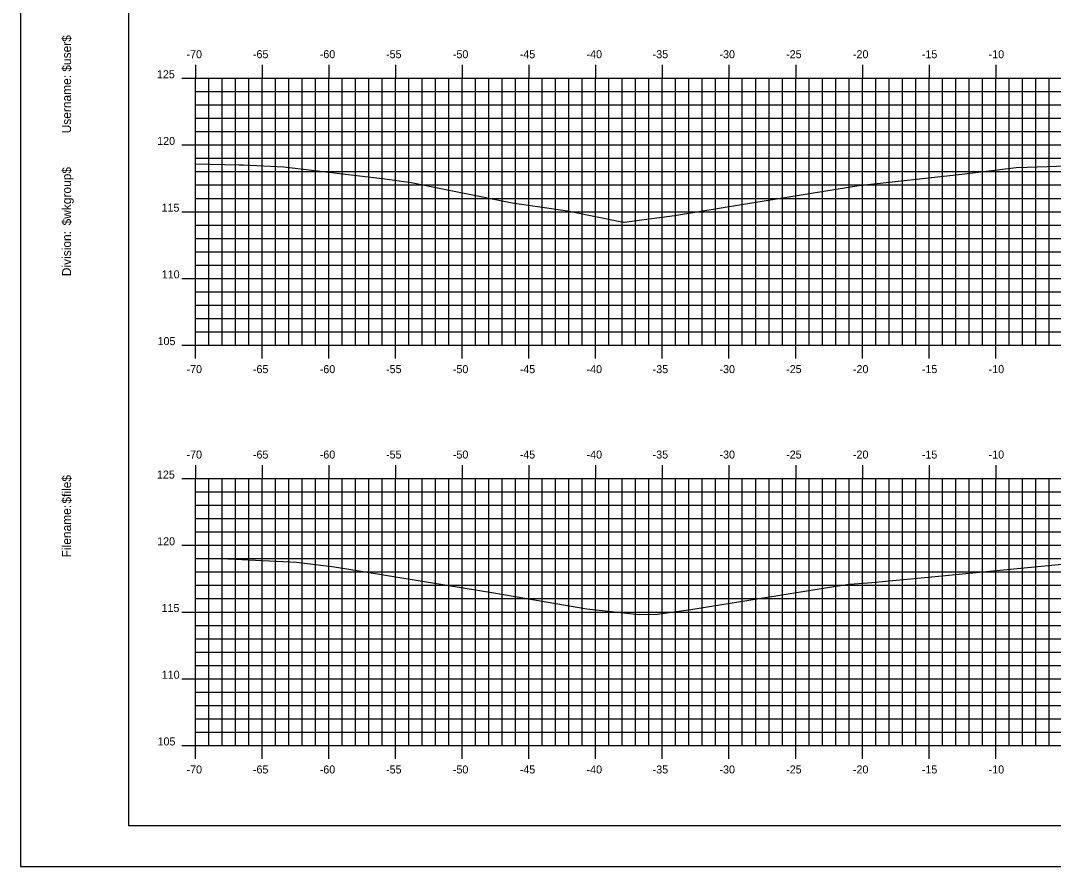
# Model space of a CAD drawing. Extents: x 853512 to 853684, y 365624 to 365734.
# Drawn here: x 853512.5 to 853589.9, y 365624 to 365687.3 of the extents above; entities that cross this region are included whole.
import ezdxf

# ---------------------------------------------------------------- set-up
doc = ezdxf.new("R2010")
doc.units = 0
for name, color, linetype in [('BORDER', 7, 'Continuous'), ('H_V ANNOTATION', 7, 'Continuous'), ('MAJOR', 7, 'Continuous'), ('MINOR', 7, 'Continuous'), ('PLOT BOUNDARY', 7, 'Continuous'), ('S_Roadway_Centerline', 7, 'Continuous')]:
    doc.layers.add(name, color=color, linetype=linetype)

msp = doc.modelspace()

# ---------------------------------------------------------------- linework, layer by layer
at = {"layer": 'BORDER'}
msp.add_lwpolyline([(853520.575, 365627.027), (853680.575, 365627.027), (853680.575, 365732.027), (853520.575, 365732.027)], close=True, dxfattribs=at)
at = {"layer": 'MAJOR'}
for p, q in [((853525.575, 365684.029), (853525.575, 365683.027)), ((853530.575, 365684.029), (853530.575, 365683.027)), ((853535.575, 365684.029), (853535.575, 365683.027)), ((853540.575, 365684.029), (853540.575, 365683.027)), ((853545.575, 365684.029), (853545.575, 365683.027)), ((853550.575, 365684.029), (853550.575, 365683.027)), ((853555.575, 365684.029), (853555.575, 365683.027)), ((853560.575, 365684.029), (853560.575, 365683.027)), ((853565.575, 365684.029), (853565.575, 365683.027)), ((853570.575, 365684.029), (853570.575, 365683.027)), ((853575.575, 365684.029), (853575.575, 365683.027)), ((853580.575, 365684.029), (853580.575, 365683.027)), ((853585.575, 365684.029), (853585.575, 365683.027)), ((853524.573, 365683.027), (853525.575, 365683.027)), ((853525.575, 365683.027), (853665.575, 365683.027)), ((853525.575, 365663.027), (853525.575, 365683.027)), ((853525.575, 365663.027), (853525.575, 365683.027)), ((853525.575, 365683.027), (853665.575, 365683.027)), ((853530.575, 365663.027), (853530.575, 365683.027)), ((853535.575, 365663.027), (853535.575, 365683.027)), ((853540.575, 365663.027), (853540.575, 365683.027)), ((853545.575, 365663.027), (853545.575, 365683.027)), ((853550.575, 365663.027), (853550.575, 365683.027)), ((853555.575, 365663.027), (853555.575, 365683.027)), ((853560.575, 365663.027), (853560.575, 365683.027)), ((853565.575, 365663.027), (853565.575, 365683.027)), ((853570.575, 365663.027), (853570.575, 365683.027)), ((853575.575, 365663.027), (853575.575, 365683.027)), ((853580.575, 365663.027), (853580.575, 365683.027)), ((853585.575, 365663.027), (853585.575, 365683.027)), ((853524.573, 365678.027), (853525.575, 365678.027)), ((853525.575, 365678.027), (853665.575, 365678.027)), ((853524.573, 365673.027), (853525.575, 365673.027)), ((853525.575, 365673.027), (853665.575, 365673.027)), ((853524.573, 365668.027), (853525.575, 365668.027)), ((853525.575, 365668.027), (853665.575, 365668.027)), ((853524.573, 365663.027), (853525.575, 365663.027)), ((853525.575, 365663.027), (853665.575, 365663.027)), ((853525.575, 365663.027), (853665.575, 365663.027)), ((853525.575, 365662.025), (853525.575, 365663.027)), ((853530.575, 365662.025), (853530.575, 365663.027)), ((853535.575, 365662.025), (853535.575, 365663.027)), ((853540.575, 365662.025), (853540.575, 365663.027)), ((853545.575, 365662.025), (853545.575, 365663.027)), ((853550.575, 365662.025), (853550.575, 365663.027)), ((853555.575, 365662.025), (853555.575, 365663.027)), ((853560.575, 365662.025), (853560.575, 365663.027)), ((853565.575, 365662.025), (853565.575, 365663.027)), ((853570.575, 365662.025), (853570.575, 365663.027)), ((853575.575, 365662.025), (853575.575, 365663.027)), ((853580.575, 365662.025), (853580.575, 365663.027)), ((853585.575, 365662.025), (853585.575, 365663.027)), ((853525.575, 365654.029), (853525.575, 365653.027)), ((853530.575, 365654.029), (853530.575, 365653.027)), ((853535.575, 365654.029), (853535.575, 365653.027)), ((853540.575, 365654.029), (853540.575, 365653.027)), ((853545.575, 365654.029), (853545.575, 365653.027)), ((853550.575, 365654.029), (853550.575, 365653.027)), ((853555.575, 365654.029), (853555.575, 365653.027)), ((853560.575, 365654.029), (853560.575, 365653.027)), ((853565.575, 365654.029), (853565.575, 365653.027)), ((853570.575, 365654.029), (853570.575, 365653.027)), ((853575.575, 365654.029), (853575.575, 365653.027)), ((853580.575, 365654.029), (853580.575, 365653.027)), ((853585.575, 365654.029), (853585.575, 365653.027)), ((853524.573, 365653.027), (853525.575, 365653.027)), ((853525.575, 365653.027), (853665.575, 365653.027)), ((853525.575, 365633.027), (853525.575, 365653.027)), ((853525.575, 365633.027), (853525.575, 365653.027)), ((853525.575, 365653.027), (853665.575, 365653.027)), ((853530.575, 365633.027), (853530.575, 365653.027)), ((853535.575, 365633.027), (853535.575, 365653.027)), ((853540.575, 365633.027), (853540.575, 365653.027)), ((853545.575, 365633.027), (853545.575, 365653.027)), ((853550.575, 365633.027), (853550.575, 365653.027)), ((853555.575, 365633.027), (853555.575, 365653.027)), ((853560.575, 365633.027), (853560.575, 365653.027)), ((853565.575, 365633.027), (853565.575, 365653.027)), ((853570.575, 365633.027), (853570.575, 365653.027)), ((853575.575, 365633.027), (853575.575, 365653.027)), ((853580.575, 365633.027), (853580.575, 365653.027)), ((853585.575, 365633.027), (853585.575, 365653.027)), ((853524.573, 365648.027), (853525.575, 365648.027)), ((853525.575, 365648.027), (853665.575, 365648.027)), ((853524.573, 365643.027), (853525.575, 365643.027)), ((853525.575, 365643.027), (853665.575, 365643.027)), ((853524.573, 365638.027), (853525.575, 365638.027)), ((853525.575, 365638.027), (853665.575, 365638.027)), ((853524.573, 365633.027), (853525.575, 365633.027)), ((853525.575, 365633.027), (853665.575, 365633.027)), ((853525.575, 365633.027), (853665.575, 365633.027)), ((853525.575, 365632.025), (853525.575, 365633.027)), ((853530.575, 365632.025), (853530.575, 365633.027)), ((853535.575, 365632.025), (853535.575, 365633.027)), ((853540.575, 365632.025), (853540.575, 365633.027)), ((853545.575, 365632.025), (853545.575, 365633.027)), ((853550.575, 365632.025), (853550.575, 365633.027)), ((853555.575, 365632.025), (853555.575, 365633.027)), ((853560.575, 365632.025), (853560.575, 365633.027)), ((853565.575, 365632.025), (853565.575, 365633.027)), ((853570.575, 365632.025), (853570.575, 365633.027)), ((853575.575, 365632.025), (853575.575, 365633.027)), ((853580.575, 365632.025), (853580.575, 365633.027)), ((853585.575, 365632.025), (853585.575, 365633.027))]:
    msp.add_line(p, q, dxfattribs=at)
at = {"layer": 'MINOR'}
for p, q in [((853526.575, 365663.027), (853526.575, 365683.027)), ((853527.575, 365663.027), (853527.575, 365683.027)), ((853528.575, 365663.027), (853528.575, 365683.027)), ((853529.575, 365663.027), (853529.575, 365683.027)), ((853531.575, 365663.027), (853531.575, 365683.027)), ((853532.575, 365663.027), (853532.575, 365683.027)), ((853533.575, 365663.027), (853533.575, 365683.027)), ((853534.575, 365663.027), (853534.575, 365683.027)), ((853536.575, 365663.027), (853536.575, 365683.027)), ((853537.575, 365663.027), (853537.575, 365683.027)), ((853538.575, 365663.027), (853538.575, 365683.027)), ((853539.575, 365663.027), (853539.575, 365683.027)), ((853541.575, 365663.027), (853541.575, 365683.027)), ((853542.575, 365663.027), (853542.575, 365683.027)), ((853543.575, 365663.027), (853543.575, 365683.027)), ((853544.575, 365663.027), (853544.575, 365683.027)), ((853546.575, 365663.027), (853546.575, 365683.027)), ((853547.575, 365663.027), (853547.575, 365683.027)), ((853548.575, 365663.027), (853548.575, 365683.027)), ((853549.575, 365663.027), (853549.575, 365683.027)), ((853551.575, 365663.027), (853551.575, 365683.027)), ((853552.575, 365663.027), (853552.575, 365683.027)), ((853553.575, 365663.027), (853553.575, 365683.027)), ((853554.575, 365663.027), (853554.575, 365683.027)), ((853556.575, 365663.027), (853556.575, 365683.027)), ((853557.575, 365663.027), (853557.575, 365683.027)), ((853558.575, 365663.027), (853558.575, 365683.027)), ((853559.575, 365663.027), (853559.575, 365683.027)), ((853561.575, 365663.027), (853561.575, 365683.027)), ((853562.575, 365663.027), (853562.575, 365683.027)), ((853563.575, 365663.027), (853563.575, 365683.027)), ((853564.575, 365663.027), (853564.575, 365683.027)), ((853566.575, 365663.027), (853566.575, 365683.027)), ((853567.575, 365663.027), (853567.575, 365683.027)), ((853568.575, 365663.027), (853568.575, 365683.027)), ((853569.575, 365663.027), (853569.575, 365683.027)), ((853571.575, 365663.027), (853571.575, 365683.027)), ((853572.575, 365663.027), (853572.575, 365683.027)), ((853573.575, 365663.027), (853573.575, 365683.027)), ((853574.575, 365663.027), (853574.575, 365683.027)), ((853576.575, 365663.027), (853576.575, 365683.027)), ((853577.575, 365663.027), (853577.575, 365683.027)), ((853578.575, 365663.027), (853578.575, 365683.027)), ((853579.575, 365663.027), (853579.575, 365683.027)), ((853581.575, 365663.027), (853581.575, 365683.027)), ((853582.575, 365663.027), (853582.575, 365683.027)), ((853583.575, 365663.027), (853583.575, 365683.027)), ((853584.575, 365663.027), (853584.575, 365683.027)), ((853586.575, 365663.027), (853586.575, 365683.027)), ((853587.575, 365663.027), (853587.575, 365683.027)), ((853588.575, 365663.027), (853588.575, 365683.027)), ((853589.575, 365663.027), (853589.575, 365683.027)), ((853525.575, 365682.027), (853665.575, 365682.027)), ((853525.575, 365682.027), (853526.577, 365682.027)), ((853525.575, 365681.027), (853665.575, 365681.027)), ((853525.575, 365681.027), (853526.577, 365681.027)), ((853525.575, 365680.027), (853665.575, 365680.027)), ((853525.575, 365680.027), (853526.577, 365680.027)), ((853525.575, 365679.027), (853665.575, 365679.027)), ((853525.575, 365679.027), (853526.577, 365679.027)), ((853525.575, 365677.027), (853665.575, 365677.027)), ((853525.575, 365677.027), (853526.577, 365677.027)), ((853525.575, 365676.027), (853665.575, 365676.027)), ((853525.575, 365676.027), (853526.577, 365676.027)), ((853525.575, 365675.027), (853665.575, 365675.027)), ((853525.575, 365675.027), (853526.577, 365675.027)), ((853525.575, 365674.027), (853665.575, 365674.027)), ((853525.575, 365674.027), (853526.577, 365674.027)), ((853525.575, 365672.027), (853665.575, 365672.027)), ((853525.575, 365672.027), (853526.577, 365672.027)), ((853525.575, 365671.027), (853665.575, 365671.027)), ((853525.575, 365671.027), (853526.577, 365671.027)), ((853525.575, 365670.027), (853665.575, 365670.027)), ((853525.575, 365670.027), (853526.577, 365670.027)), ((853525.575, 365669.027), (853665.575, 365669.027)), ((853525.575, 365669.027), (853526.577, 365669.027)), ((853525.575, 365667.027), (853665.575, 365667.027)), ((853525.575, 365667.027), (853526.577, 365667.027)), ((853525.575, 365666.027), (853665.575, 365666.027)), ((853525.575, 365666.027), (853526.577, 365666.027)), ((853525.575, 365665.027), (853665.575, 365665.027)), ((853525.575, 365665.027), (853526.577, 365665.027)), ((853525.575, 365664.027), (853665.575, 365664.027)), ((853525.575, 365664.027), (853526.577, 365664.027)), ((853526.575, 365633.027), (853526.575, 365653.027)), ((853527.575, 365633.027), (853527.575, 365653.027)), ((853528.575, 365633.027), (853528.575, 365653.027)), ((853529.575, 365633.027), (853529.575, 365653.027)), ((853531.575, 365633.027), (853531.575, 365653.027)), ((853532.575, 365633.027), (853532.575, 365653.027)), ((853533.575, 365633.027), (853533.575, 365653.027)), ((853534.575, 365633.027), (853534.575, 365653.027)), ((853536.575, 365633.027), (853536.575, 365653.027)), ((853537.575, 365633.027), (853537.575, 365653.027)), ((853538.575, 365633.027), (853538.575, 365653.027)), ((853539.575, 365633.027), (853539.575, 365653.027)), ((853541.575, 365633.027), (853541.575, 365653.027)), ((853542.575, 365633.027), (853542.575, 365653.027)), ((853543.575, 365633.027), (853543.575, 365653.027)), ((853544.575, 365633.027), (853544.575, 365653.027)), ((853546.575, 365633.027), (853546.575, 365653.027)), ((853547.575, 365633.027), (853547.575, 365653.027)), ((853548.575, 365633.027), (853548.575, 365653.027)), ((853549.575, 365633.027), (853549.575, 365653.027)), ((853551.575, 365633.027), (853551.575, 365653.027)), ((853552.575, 365633.027), (853552.575, 365653.027)), ((853553.575, 365633.027), (853553.575, 365653.027)), ((853554.575, 365633.027), (853554.575, 365653.027)), ((853556.575, 365633.027), (853556.575, 365653.027)), ((853557.575, 365633.027), (853557.575, 365653.027)), ((853558.575, 365633.027), (853558.575, 365653.027)), ((853559.575, 365633.027), (853559.575, 365653.027)), ((853561.575, 365633.027), (853561.575, 365653.027)), ((853562.575, 365633.027), (853562.575, 365653.027)), ((853563.575, 365633.027), (853563.575, 365653.027)), ((853564.575, 365633.027), (853564.575, 365653.027)), ((853566.575, 365633.027), (853566.575, 365653.027)), ((853567.575, 365633.027), (853567.575, 365653.027)), ((853568.575, 365633.027), (853568.575, 365653.027)), ((853569.575, 365633.027), (853569.575, 365653.027)), ((853571.575, 365633.027), (853571.575, 365653.027)), ((853572.575, 365633.027), (853572.575, 365653.027)), ((853573.575, 365633.027), (853573.575, 365653.027)), ((853574.575, 365633.027), (853574.575, 365653.027)), ((853576.575, 365633.027), (853576.575, 365653.027)), ((853577.575, 365633.027), (853577.575, 365653.027)), ((853578.575, 365633.027), (853578.575, 365653.027)), ((853579.575, 365633.027), (853579.575, 365653.027)), ((853581.575, 365633.027), (853581.575, 365653.027)), ((853582.575, 365633.027), (853582.575, 365653.027)), ((853583.575, 365633.027), (853583.575, 365653.027)), ((853584.575, 365633.027), (853584.575, 365653.027)), ((853586.575, 365633.027), (853586.575, 365653.027)), ((853587.575, 365633.027), (853587.575, 365653.027)), ((853588.575, 365633.027), (853588.575, 365653.027)), ((853589.575, 365633.027), (853589.575, 365653.027)), ((853525.575, 365652.027), (853665.575, 365652.027)), ((853525.575, 365652.027), (853526.577, 365652.027)), ((853525.575, 365651.027), (853665.575, 365651.027)), ((853525.575, 365651.027), (853526.577, 365651.027)), ((853525.575, 365650.027), (853665.575, 365650.027)), ((853525.575, 365650.027), (853526.577, 365650.027)), ((853525.575, 365649.027), (853665.575, 365649.027)), ((853525.575, 365649.027), (853526.577, 365649.027)), ((853525.575, 365647.027), (853665.575, 365647.027)), ((853525.575, 365647.027), (853526.577, 365647.027)), ((853525.575, 365646.027), (853665.575, 365646.027)), ((853525.575, 365646.027), (853526.577, 365646.027)), ((853525.575, 365645.027), (853665.575, 365645.027)), ((853525.575, 365645.027), (853526.577, 365645.027)), ((853525.575, 365644.027), (853665.575, 365644.027)), ((853525.575, 365644.027), (853526.577, 365644.027)), ((853525.575, 365642.027), (853665.575, 365642.027)), ((853525.575, 365642.027), (853526.577, 365642.027)), ((853525.575, 365641.027), (853665.575, 365641.027)), ((853525.575, 365641.027), (853526.577, 365641.027)), ((853525.575, 365640.027), (853665.575, 365640.027)), ((853525.575, 365640.027), (853526.577, 365640.027)), ((853525.575, 365639.027), (853665.575, 365639.027)), ((853525.575, 365639.027), (853526.577, 365639.027)), ((853525.575, 365637.027), (853665.575, 365637.027)), ((853525.575, 365637.027), (853526.577, 365637.027)), ((853525.575, 365636.027), (853665.575, 365636.027)), ((853525.575, 365636.027), (853526.577, 365636.027)), ((853525.575, 365635.027), (853665.575, 365635.027)), ((853525.575, 365635.027), (853526.577, 365635.027)), ((853525.575, 365634.027), (853665.575, 365634.027)), ((853525.575, 365634.027), (853526.577, 365634.027))]:
    msp.add_line(p, q, dxfattribs=at)
at = {"layer": 'PLOT BOUNDARY'}
msp.add_lwpolyline([(853512.481, 365623.968), (853682.481, 365623.968), (853682.481, 365733.968), (853512.481, 365733.968)], close=True, dxfattribs=at)
at = {"layer": 'S_Roadway_Centerline'}
for points in [[(853525.575, 365676.623), (853528.871, 365676.542), (853528.939, 365676.539), (853529.181, 365676.533), (853532.205, 365676.389), (853539.774, 365675.492), (853541.752, 365675.216), (853549.324, 365673.701), (853553.474, 365673.079), (853557.66, 365672.232), (853557.728, 365672.248), (853561.495, 365672.735), (853566.524, 365673.574), (853575.319, 365674.99), (853583.031, 365675.837), (853587.107, 365676.343), (853587.935, 365676.351), (853589.415, 365676.405), (853599.207, 365676.766)], [(853525.575, 365647.046), (853528.01, 365647.007), (853531.648, 365646.83), (853533.155, 365646.773), (853536.009, 365646.409), (853547.938, 365644.461), (853554.917, 365643.262), (853558.849, 365642.834), (853560.204, 365642.873), (853562.724, 365643.211), (853573.581, 365644.955), (853574.622, 365645.11), (853576.291, 365645.245), (853581.032, 365645.7), (853591.548, 365646.72)]]:
    msp.add_lwpolyline(points, dxfattribs=at)

# ---------------------------------------------------------------- texts
at = {"layer": 'BORDER'}
for s, p in [('$user$', (853516.26, 365683.518)), ('Username:', (853516.26, 365678.895)), ('$wkgroup$', (853516.26, 365671.996)), ('Division:', (853516.26, 365668.193)), ('$file$', (853516.26, 365651.152)), ('Filename:', (853516.26, 365647.125))]:
    msp.add_text(s, height=0.6696, rotation=90, dxfattribs=at).set_placement(p)
at = {"layer": 'H_V ANNOTATION'}
for s, p in [('-70', (853524.916, 365684.527)), ('-65', (853529.892, 365684.527)), ('-60', (853534.9, 365684.527)), ('-55', (853539.871, 365684.527)), ('-50', (853544.879, 365684.527)), ('-45', (853549.892, 365684.527)), ('-40', (853554.9, 365684.527)), ('-35', (853559.855, 365684.527)), ('-30', (853564.863, 365684.527)), ('-25', (853569.86, 365684.527)), ('-20', (853574.868, 365684.527)), ('-15', (853580.031, 365684.527)), ('-10', (853585.039, 365684.527)), ('125', (853522.699, 365683.027)), ('120', (853522.715, 365678.027)), ('115', (853523.042, 365673.027)), ('110', (853523.058, 365668.027)), ('105', (853522.742, 365663.027)), ('-70', (853524.916, 365660.927)), ('-65', (853529.892, 365660.927)), ('-60', (853534.9, 365660.927)), ('-55', (853539.871, 365660.927)), ('-50', (853544.879, 365660.927)), ('-45', (853549.892, 365660.927)), ('-40', (853554.9, 365660.927)), ('-35', (853559.855, 365660.927)), ('-30', (853564.863, 365660.927)), ('-25', (853569.86, 365660.927)), ('-20', (853574.868, 365660.927)), ('-15', (853580.031, 365660.927)), ('-10', (853585.039, 365660.927)), ('-70', (853524.916, 365654.527)), ('-65', (853529.892, 365654.527)), ('-60', (853534.9, 365654.527)), ('-55', (853539.871, 365654.527)), ('-50', (853544.879, 365654.527)), ('-45', (853549.892, 365654.527)), ('-40', (853554.9, 365654.527)), ('-35', (853559.855, 365654.527)), ('-30', (853564.863, 365654.527)), ('-25', (853569.86, 365654.527)), ('-20', (853574.868, 365654.527)), ('-15', (853580.031, 365654.527)), ('-10', (853585.039, 365654.527)), ('125', (853522.699, 365653.027)), ('120', (853522.715, 365648.027)), ('115', (853523.042, 365643.027)), ('110', (853523.058, 365638.027)), ('105', (853522.742, 365633.027)), ('-70', (853524.916, 365630.927)), ('-65', (853529.892, 365630.927)), ('-60', (853534.9, 365630.927)), ('-55', (853539.871, 365630.927)), ('-50', (853544.879, 365630.927)), ('-45', (853549.892, 365630.927)), ('-40', (853554.9, 365630.927)), ('-35', (853559.855, 365630.927)), ('-30', (853564.863, 365630.927)), ('-25', (853569.86, 365630.927)), ('-20', (853574.868, 365630.927)), ('-15', (853580.031, 365630.927)), ('-10', (853585.039, 365630.927))]:
    msp.add_text(s, height=0.6, dxfattribs=at).set_placement(p)
at = {"layer": 'MAJOR'}
for p in [(853525.57, 365663.027), (853525.57, 365633.027)]:
    msp.add_text('-', height=0.006, dxfattribs=at).set_placement(p)

doc.saveas('drawing.dxf')
